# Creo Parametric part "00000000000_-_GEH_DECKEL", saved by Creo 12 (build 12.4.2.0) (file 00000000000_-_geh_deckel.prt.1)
Units: Custom; MM, KILOGRAM, SECS

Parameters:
  PTC_WM_ITERATION = "0"
  PTC_WM_VERSION = "-.0"
  PTC_WM_LIFECYCLE_STATE = "In Work"
  PTC_WM_LIFECYCLE = "MO_CADDocument"
  PTC_WM_CREATED_BY = "Maximilian Roepper (Z0017RMS: MO)"
  PTC_WM_CREATED_ON = "18-Sep-26 11:36:42 AM"
  PTC_WM_MODIFIED_BY = "Maximilian Roepper (Z0017RMS: MO)"
  PTC_WM_MODIFIED_ON = "02-Oct-26 01:21:57 PM"
  PDMLINKNUMBER = "PDM000071455264"
  PTC_WM_NAME = "00000000000_-_geh_deckel.prt"
  PTC_WM_NUMBER = "PDM000071455264"

Other parameters: WEIGHT, WEIGHT_FACTOR, WEIGHT_ADD, _MASS_TEMP, _DIFF_TEMP, MC_ERRORS, SUPPLIER

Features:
  1. coordinate system
  2. datum plane "PRT_YZ"
  3. datum plane "PRT_XY"
  4. datum plane "PRT_XZ"
  5. coordinate system
  6. datum axis
  7. datum axis
  8. datum axis
  9. coordinate system
  10. datum plane "DTM1"
  11. datum plane "DTM2"
  12. protrusion
  13. protrusion
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
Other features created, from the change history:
  extrusion

Other named items: PRT, SIEMENS_MO, DRW_VIEW_ORG, KOERPER, AUFL, FREISCHNITT_AUFL_BUTZ, PRT_X, PRT_Y, PRT_Z, CS0, AD176, AD178, AD180, AD182, AD184, ROUGH_GROB

Layers: 00_STD_CSYS-KSYS, 01_STD_PLANES-EBENEN, 02_STD_AXES-ACHSEN, 03_STD_CSYS-KSYS, 04_PLANES-EBENEN, 05_AXES-ACHSEN, 10_ROUNDS-RUNDUNGEN, 16_CUTS-MATERIALSCHNITTE, 24_IMPORT_FEAT-IMPORT_KE

Surfaces: 33 plane, 12 cylinder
